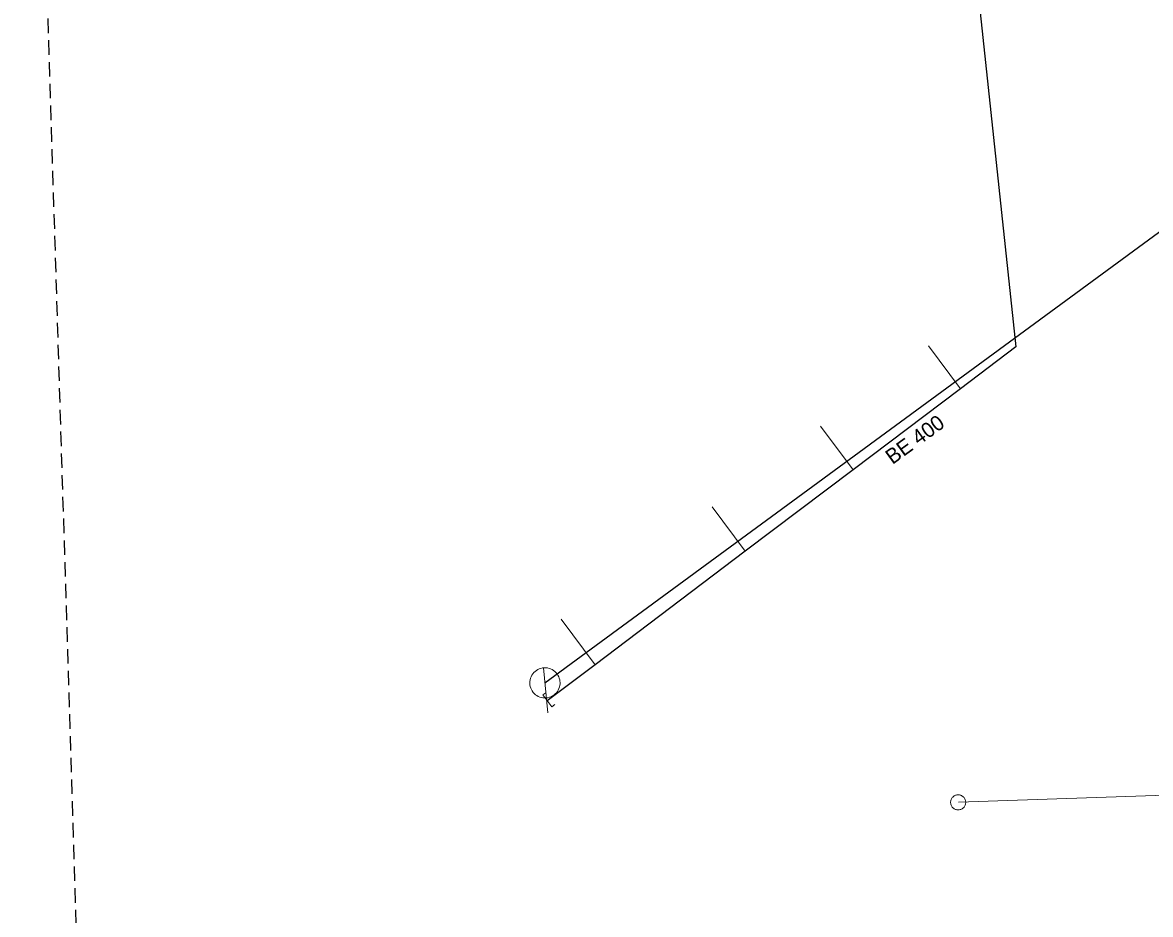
# Model space of a CAD drawing. Extents: x -777996 to -777727, y -976581 to -976199.
# Drawn here: x -777995.4 to -777920.7, y -976316.9 to -976257.9 of the extents above; entities that cross this region are included whole.
import ezdxf

# ---------------------------------------------------------------- set-up
doc = ezdxf.new("R2010")
doc.units = 0
doc.header["$LTSCALE"] = 0.32
doc.linetypes.add('MEDIUM_DASHED', pattern=[4.5, 3, -1.5])
for name, color, linetype, lineweight in [('1', 7, 'MEDIUM_DASHED', 25), ('13', 7, 'Continuous', 13), ('14', 7, 'Continuous', 25), ('17', 7, 'Continuous', 25), ('22', 7, 'Continuous', 13), ('23', 7, 'Continuous', 13), ('47', 7, 'Continuous', 13)]:
    doc.layers.add(name, color=color, linetype=linetype, lineweight=lineweight)

msp = doc.modelspace()

# ---------------------------------------------------------------- linework, layer by layer
at = {"layer": '1'}
msp.add_lwpolyline([(-777995.417, -976203.033), (-777848.18, -976198.846), (-777864.927, -976230.247), (-777726.762, -976491.225), (-777789.565, -976581.242), (-777941.686, -976558.215), (-777989.136, -976405.396)], close=True, dxfattribs=at)
at = {"layer": '13'}
for p, q in [((-777933.318, -976282.133), (-777935.43, -976279.294)), ((-777940.43, -976287.506), (-777942.581, -976284.613)), ((-777947.561, -976292.896), (-777949.754, -976289.945)), ((-777957.508, -976300.412), (-777959.76, -976297.384)), ((-777911.609, -976308.78), (-777933.447, -976309.493))]:
    msp.add_line(p, q, dxfattribs=at)
at = {"layer": '14'}
msp.add_lwpolyline([(-777960.831, -976301.607), (-777912.32, -976266.008), (-777896.01, -976225.129)], dxfattribs=at)
at = {"layer": '17'}
msp.add_lwpolyline([(-777934.804, -976231.131), (-777929.646, -976279.357), (-777933.318, -976282.133), (-777940.43, -976287.506), (-777947.561, -976292.896), (-777957.508, -976300.412), (-777960.673, -976302.804)], dxfattribs=at)
at = {"layer": '22'}
msp.add_line((-777960.645, -976303.598), (-777960.923, -976300.611), dxfattribs=at)
msp.add_lwpolyline([(-777959.835, -976301.514), (-777959.851, -976301.406), (-777959.879, -976301.301), (-777959.918, -976301.198), (-777959.968, -976301.101), (-777960.028, -976301.009), (-777960.098, -976300.925), (-777960.178, -976300.849), (-777960.264, -976300.783), (-777960.358, -976300.726), (-777960.457, -976300.679), (-777960.56, -976300.644), (-777960.668, -976300.621), (-777960.777, -976300.609), (-777960.886, -976300.609), (-777960.995, -976300.621), (-777961.102, -976300.645), (-777961.206, -976300.68), (-777961.305, -976300.726), (-777961.398, -976300.784), (-777961.484, -976300.85), (-777961.564, -976300.927), (-777961.633, -976301.011), (-777961.694, -976301.103), (-777961.744, -976301.2), (-777961.783, -976301.302), (-777961.81, -976301.408), (-777961.826, -976301.517), (-777961.83, -976301.626), (-777961.822, -976301.735), (-777961.802, -976301.843), (-777961.771, -976301.947), (-777961.728, -976302.048), (-777961.674, -976302.143), (-777961.611, -976302.233), (-777961.537, -976302.314), (-777961.456, -976302.387), (-777961.367, -976302.451), (-777961.271, -976302.505), (-777961.171, -976302.548), (-777961.066, -976302.579), (-777960.958, -976302.599), (-777960.849, -976302.607), (-777960.739, -976302.603), (-777960.631, -976302.587), (-777960.525, -976302.559), (-777960.423, -976302.52), (-777960.325, -976302.47), (-777960.234, -976302.409), (-777960.15, -976302.339), (-777960.074, -976302.261), (-777960.006, -976302.174), (-777959.95, -976302.081), (-777959.903, -976301.982), (-777959.868, -976301.878), (-777959.844, -976301.771), (-777959.832, -976301.662), (-777959.832, -976301.552)], close=True, dxfattribs=at)
at = {"layer": '23'}
for points in [[(-777932.969, -976309.492), (-777932.974, -976309.439), (-777932.985, -976309.387), (-777933.002, -976309.339), (-777933.023, -976309.291), (-777933.049, -976309.245), (-777933.08, -976309.203), (-777933.115, -976309.164), (-777933.153, -976309.129), (-777933.196, -976309.098), (-777933.241, -976309.072), (-777933.288, -976309.05), (-777933.339, -976309.034), (-777933.39, -976309.022), (-777933.441, -976309.017), (-777933.493, -976309.016), (-777933.547, -976309.023), (-777933.596, -976309.032), (-777933.648, -976309.049), (-777933.694, -976309.069), (-777933.74, -976309.095), (-777933.783, -976309.128), (-777933.822, -976309.162), (-777933.857, -976309.202), (-777933.888, -976309.243), (-777933.914, -976309.288), (-777933.935, -976309.337), (-777933.951, -976309.385), (-777933.962, -976309.437), (-777933.967, -976309.489), (-777933.968, -976309.541), (-777933.963, -976309.593), (-777933.952, -976309.645), (-777933.936, -976309.695), (-777933.915, -976309.742), (-777933.889, -976309.786), (-777933.858, -976309.829), (-777933.823, -976309.869), (-777933.784, -976309.904), (-777933.742, -976309.935)], [(-777933.742, -976309.935), (-777933.698, -976309.961), (-777933.649, -976309.982), (-777933.6, -976309.999), (-777933.548, -976310.009), (-777933.496, -976310.014), (-777933.444, -976310.015), (-777933.393, -976310.009), (-777933.341, -976309.999), (-777933.29, -976309.983), (-777933.243, -976309.962), (-777933.197, -976309.936), (-777933.155, -976309.906), (-777933.117, -976309.87), (-777933.081, -976309.832), (-777933.051, -976309.79), (-777933.024, -976309.744), (-777933.002, -976309.696), (-777932.986, -976309.646), (-777932.976, -976309.595), (-777932.97, -976309.544), (-777932.969, -976309.492), (-777932.974, -976309.439), (-777932.985, -976309.387), (-777933.002, -976309.339), (-777933.023, -976309.291), (-777933.049, -976309.245), (-777933.08, -976309.203), (-777933.115, -976309.164), (-777933.153, -976309.129), (-777933.196, -976309.098), (-777933.241, -976309.072), (-777933.288, -976309.05), (-777933.339, -976309.034), (-777933.39, -976309.022), (-777933.441, -976309.017), (-777933.493, -976309.016), (-777933.547, -976309.023), (-777933.596, -976309.032), (-777933.648, -976309.049)], [(-777933.648, -976309.049), (-777933.694, -976309.069), (-777933.74, -976309.095), (-777933.783, -976309.128), (-777933.822, -976309.162), (-777933.857, -976309.202), (-777933.888, -976309.243), (-777933.914, -976309.288), (-777933.935, -976309.337), (-777933.951, -976309.385), (-777933.962, -976309.437), (-777933.967, -976309.489), (-777933.968, -976309.541), (-777933.963, -976309.593), (-777933.952, -976309.645), (-777933.936, -976309.695), (-777933.915, -976309.742), (-777933.889, -976309.786), (-777933.858, -976309.829), (-777933.823, -976309.869), (-777933.784, -976309.904), (-777933.742, -976309.935), (-777933.698, -976309.961), (-777933.649, -976309.982), (-777933.6, -976309.999), (-777933.548, -976310.009), (-777933.496, -976310.014), (-777933.444, -976310.015), (-777933.393, -976310.009), (-777933.341, -976309.999), (-777933.29, -976309.983), (-777933.243, -976309.962), (-777933.197, -976309.936), (-777933.155, -976309.906), (-777933.117, -976309.87), (-777933.081, -976309.832), (-777933.051, -976309.79), (-777933.024, -976309.744), (-777933.002, -976309.696), (-777932.986, -976309.646)], [(-777932.986, -976309.646), (-777932.976, -976309.595), (-777932.97, -976309.544), (-777932.969, -976309.492)]]:
    msp.add_lwpolyline(points, dxfattribs=at)
at = {"layer": '47'}
msp.add_lwpolyline([(-777960.172, -976303.047), (-777960.373, -976303.199), (-777960.972, -976302.408), (-777960.77, -976302.256)], dxfattribs=at)

# ---------------------------------------------------------------- texts
at = {"layer": '1'}
msp.add_text('BE 400', height=1, rotation=36, dxfattribs=at).set_placement((-777937.819, -976287.182))

doc.saveas('drawing.dxf')
